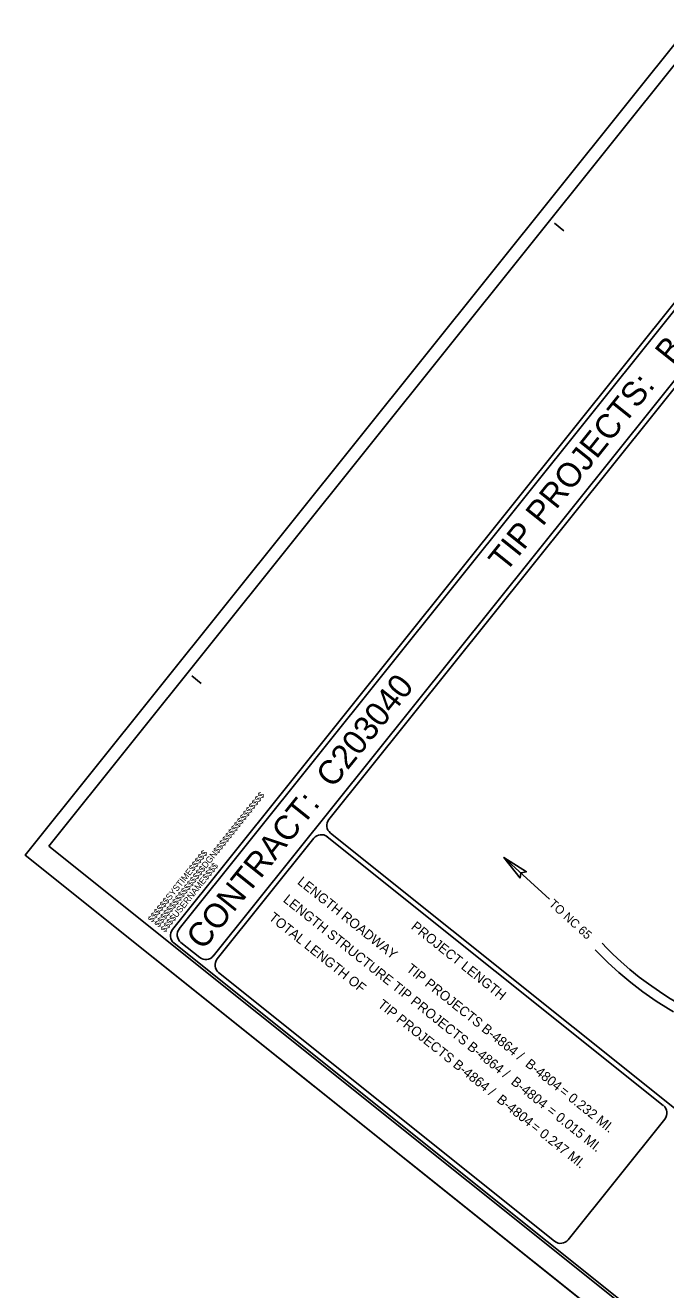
# Model space of a CAD drawing. Extents: x 1730256 to 1738218, y 910410 to 917906.
# Drawn here: x 1732765 to 1734090, y 915111 to 917728 of the extents above; entities that cross this region are included whole.
import ezdxf

# ---------------------------------------------------------------- set-up
doc = ezdxf.new("R2010")
doc.units = 0
for name, color, linetype in [('Old_Level_3', 7, 'Continuous'), ('Old_Level_38', 7, 'Continuous'), ('Old_Level_9', 7, 'Continuous'), ('Prop DSN Text', 7, 'Continuous'), ('Prop Terminator CELL', 7, 'Continuous'), ('Sheet Cutting Line CELL', 7, 'Continuous'), ('Sheet Data Field CELL', 7, 'Continuous'), ('Sheet Plot Border Inside CELL', 7, 'Continuous'), ('Sheet Title CELL', 7, 'Continuous')]:
    doc.layers.add(name, color=color, linetype=linetype)

msp = doc.modelspace()

# ---------------------------------------------------------------- linework, layer by layer
at = {"layer": 'Old_Level_3'}
for points in [[(1734116.3, 915704), (1734096.5, 915715.8), (1734076.9, 915728.5), (1734054.2, 915744.2), (1734034.9, 915758.6), (1734015.5, 915774.5), (1733997.9, 915789.8), (1733980.5, 915806.2), (1733968.3, 915818.6), (1733958.7, 915828.4)], [(1734106, 915686.6), (1734095.3, 915692.8), (1734070.1, 915708.4), (1734042.7, 915728.1), (1734017.8, 915747.1), (1733993.1, 915767.7), (1733971.1, 915787.9), (1733956.1, 915802.5), (1733943.7, 915815.2)]]:
    msp.add_lwpolyline(points, dxfattribs=at)
at = {"layer": 'Old_Level_9'}
msp.add_line((1733849.1, 915919.9), (1733755.1, 916006.2), dxfattribs=at)
at = {"layer": 'Prop Terminator CELL'}
msp.add_lwpolyline([(1733788.6, 915962.9), (1733755.1, 916006.2), (1733801.6, 915976.6), (1733790, 915974.2)], close=True, dxfattribs=at)
at = {"layer": 'Sheet Cutting Line CELL'}
for p, q in [((1734139.9, 917728.5), (1732765.3, 916010.8)), ((1732765.3, 916010.8), (1735394.8, 913906.4))]:
    msp.add_line(p, q, dxfattribs=at)
at = {"layer": 'Sheet Data Field CELL'}
msp.add_line((1733057.3, 915841.2), (1733057.3, 915841.2), dxfattribs=at)
msp.add_lwpolyline([(1736769.5, 915624), (1734139.9, 917728.5), (1732765.3, 916010.8), (1735394.8, 913906.4)], close=True, dxfattribs=at)
at = {"layer": 'Sheet Plot Border Inside CELL'}
msp.add_lwpolyline([(1732813.6, 916029.6), (1735415.9, 913947), (1736734.4, 915594.6), (1734132.1, 917677.2)], close=True, dxfattribs=at)
at = {"layer": 'Sheet Title CELL'}
for p, q in [((1733154.1, 915802.1), (1734428.8, 917394.9)), ((1733393.1, 916084.7), (1734436.6, 917388.6)), ((1733859.5, 917318.9), (1733879, 917303.3)), ((1733859.5, 917318.9), (1733879, 917303.3)), ((1733109.7, 916382), (1733129.2, 916366.4)), ((1733109.7, 916382), (1733129.2, 916366.4)), ((1733361.9, 916045.7), (1733161.9, 915795.9)), ((1733389.9, 916048.8), (1734084.8, 915492.7)), ((1733396.2, 916056.6), (1735613.6, 914282.1)), ((1733057.3, 915841.2), (1733057.3, 915841.2)), ((1733057.3, 915841.2), (1733057.3, 915841.2)), ((1733057.3, 915841.2), (1733057.3, 915841.2)), ((1733057.3, 915841.2), (1733057.3, 915841.2)), ((1734088, 915464.6), (1733888, 915214.8))]:
    msp.add_line(p, q, dxfattribs=at)
for points in [[(1734356.9, 917465.1), (1733069.8, 915856.8)], [(1734356.9, 917465.1), (1733069.8, 915856.8)], [(1734358.5, 917451.1), (1733083.8, 915858.4)], [(1733072.9, 915828.7), (1735383.9, 913979.1)], [(1733086.9, 915830.3), (1733126, 915799)], [(1733165, 915767.7), (1733859.9, 915211.6)]]:
    msp.add_lwpolyline(points, dxfattribs=at)
for centre, start, end in [((1733408.8, 916072.3), 141.3297, 231.3297), ((1733377.5, 916033.3), 51.3297, 141.3297), ((1733085.4, 915844.4), 141.3297, 231.3297), ((1733099.5, 915845.9), 141.3297, 231.3297), ((1733138.5, 915814.7), 231.3297, 321.3297), ((1733177.6, 915783.4), 141.3297, 231.3297), ((1734072.4, 915477.2), 321.3297, 51.3297), ((1733872.5, 915227.3), 231.3297, 321.3297)]:
    msp.add_arc(centre, 20, start, end, dxfattribs=at)

# ---------------------------------------------------------------- texts
at = {"layer": 'Old_Level_38'}
for s, p in [('LENGTH ROADWAY', (1733326.5, 915952.7)), ('LENGTH STRUCTURE', (1733297, 915915.7)), ('TOTAL LENGTH OF', (1733267.4, 915878.8)), ('TIP PROJECTS B-4864 /  B-4804', (1733551.8, 915772.4)), ('TIP PROJECTS B-4864 /  B-4804', (1733522.2, 915735.5)), ('TIP PROJECTS B-4864 /  B-4804', (1733492.7, 915698.5)), ('= 0.232 MI.', (1733868.3, 915519.1)), ('= 0.015 MI.', (1733842.4, 915479.2)), ('= 0.247 MI.', (1733809.1, 915445.3))]:
    msp.add_text(s, height=20, rotation=321.3297, dxfattribs=at).set_placement(p)
at = {"layer": 'Prop DSN Text'}
msp.add_text('TO NC 65', height=18, rotation=317.6535, dxfattribs=at).set_placement((1733846.9, 915908))
at = {"layer": 'Sheet Title CELL'}
for s, height, rotation, p in [('B-4864 / B-4804', 50, 51.3297, (1734103, 917024.3)), ('TIP PROJECTS:', 50, 51.3297, (1733758.6, 916594)), ('C203040', 50, 51.3297, (1733401.5, 916147.7)), ('$$$$$$$$$$$$$$$$DGN$$$$$$$$$$$$$$$$', 13.125, 51.3297, (1733041.3, 915860.4)), ('CONTRACT:', 50, 51.3297, (1733133.1, 915812.4)), ('$$$$$$SYSTIME$$$$$', 13.125, 51.3297, (1733027.8, 915870.6)), ('$$$$USERNAME$$$$', 13.125, 51.3297, (1733053.9, 915849.8)), ('PROJECT LENGTH', 19.999, 321.3297, (1733561.7, 915859.8))]:
    msp.add_text(s, height=height, rotation=rotation, dxfattribs=at).set_placement(p)

doc.saveas('drawing.dxf')
